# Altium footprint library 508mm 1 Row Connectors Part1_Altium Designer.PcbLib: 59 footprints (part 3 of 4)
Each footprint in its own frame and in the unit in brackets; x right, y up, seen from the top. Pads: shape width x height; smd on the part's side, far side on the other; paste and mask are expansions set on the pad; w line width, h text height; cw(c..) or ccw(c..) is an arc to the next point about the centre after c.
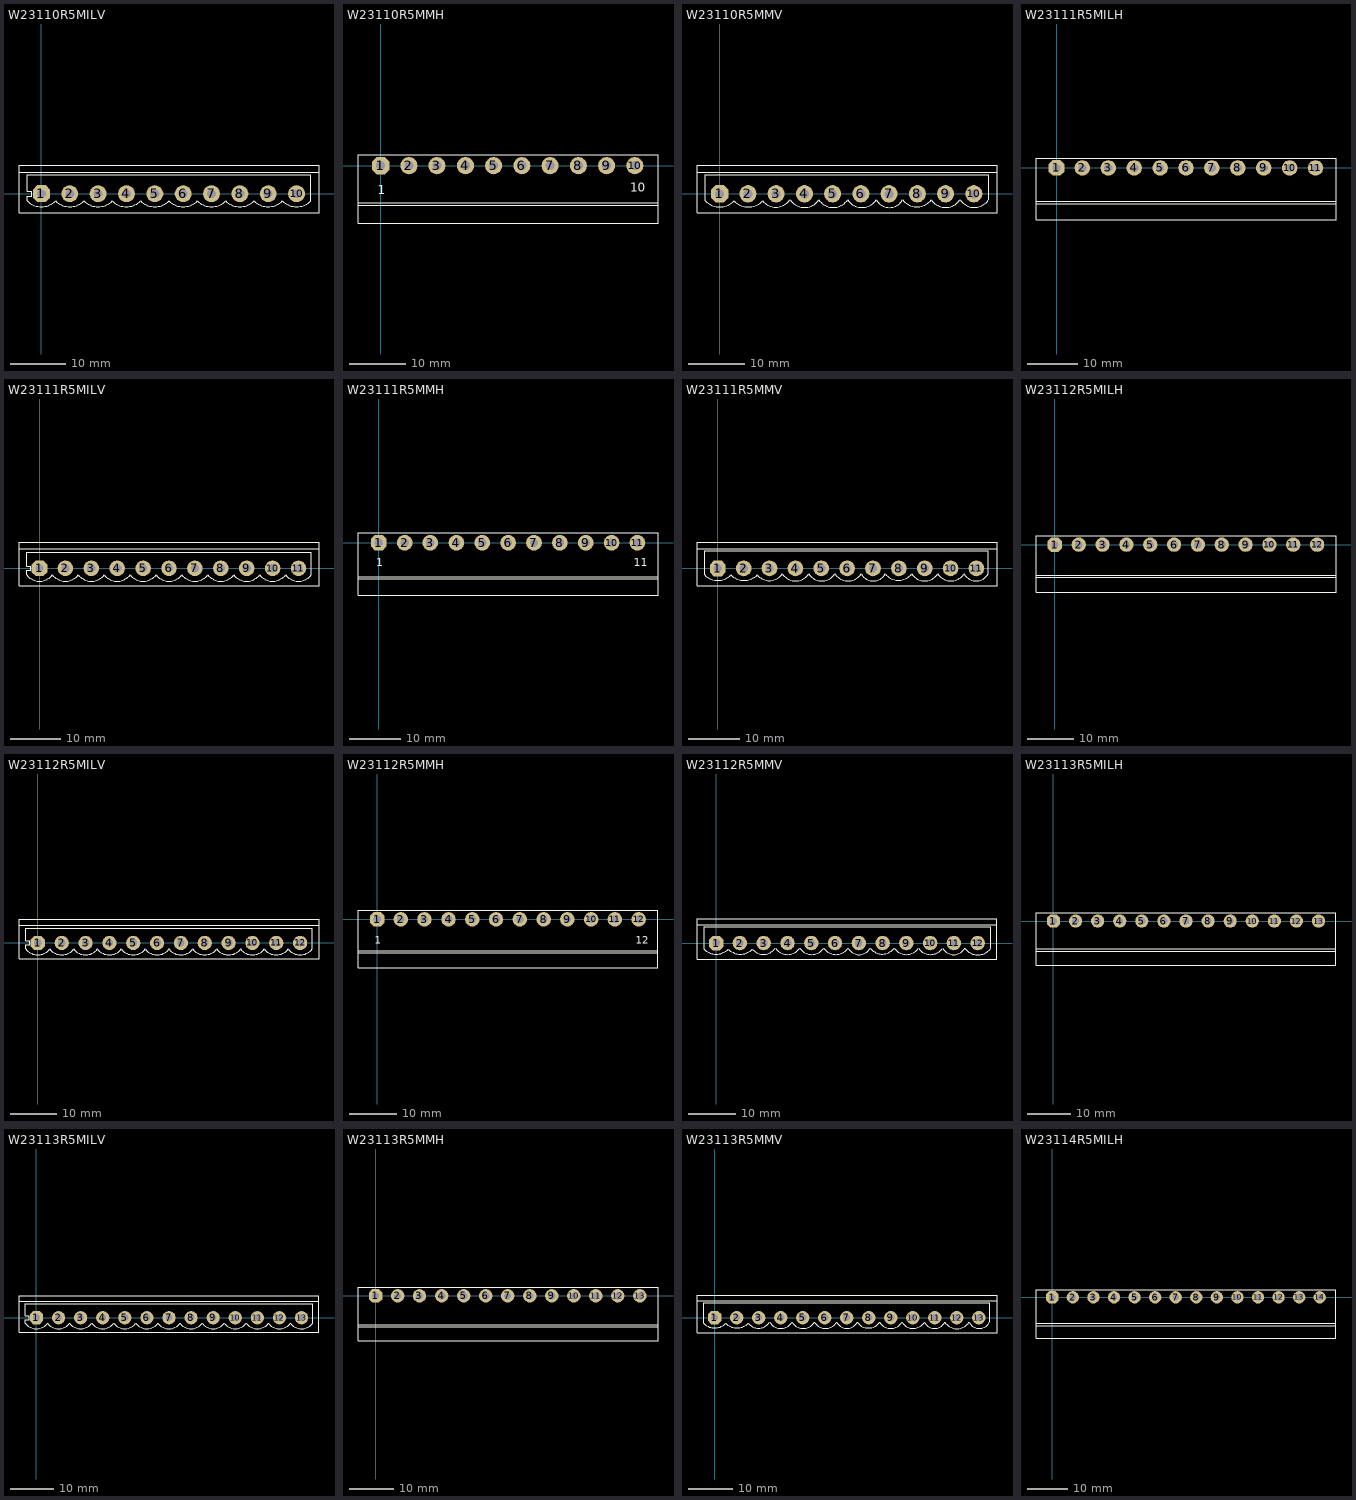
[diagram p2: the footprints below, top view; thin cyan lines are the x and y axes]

## W23110R5MILV [mil] "M.Hariri (Altium Designer)"
pads (10):
  oct 120x120 hole 62.99: 1(0,0)
  round 120 hole 62.99: 2(200,0) 3(400,0) 4(600,0) 5(800,0) 6(1000,0) 7(1200,0) 8(1400,0) 9(1600,0) 10(1800,0)
Top Overlay:
  lines w8: -158.33,150 1958.33,150 ; -100.17,-50.17 ccw(c0,50) 100.17,-50.17 ; -100,-50 -100,-16.67 -66.67,-16.67 -66.67,16.67 -100,16.67 -100,133.33 1900,133.33 1900,-50 ; 99.83,-50.17 ccw(c200,50) 300.17,-50.17 ; 299.83,-50.17 ccw(c400,50) 500.17,-50.17 ; 499.83,-50.17 ccw(c600,50) 700.17,-50.17 ; 699.83,-50.17 ccw(c800,50) 900.17,-50.17 ; 899.83,-50.17 ccw(c1000,50) 1100.17,-50.17 ; 1099.83,-50.17 ccw(c1200,50) 1300.17,-50.17 ; 1299.83,-50.17 ccw(c1400,50) 1500.17,-50.17 ; 1499.83,-50.17 ccw(c1600,50) 1700.17,-50.17 ; 1699.83,-50.17 ccw(c1800,50) 1900.17,-50.17 ; -158.33,-133.33 -158.33,200 1958.33,200 1958.33,-133.33 -158.33,-133.33

## W23110R5MMH [mil] "M.Hariri (Altium Designer)"
pads (10):
  oct 120x120 hole 62.99: 1(0,0)
  round 120 hole 62.99: 2(196.67,0) 3(391.67,0) 4(590.83,0) 5(787.5,0) 6(984.17,0) 7(1180.83,0) 8(1378.33,0) 9(1575,0) 10(1771.67,0)
Top Overlay:
  lines w8: -158.33,-275 1933.33,-275 ; -158.33,-258.33 1933.33,-258.33 ; -158.33,-400 -158.33,75 1933.33,75 1933.33,-400 -158.33,-400
  text "10" at 1740,-180 h60
  text "1" at -20,-200 h60

## W23110R5MMV [mil] "M.Hariri (Altium Designer)"
pads (10):
  oct 120x120 hole 62.99: 1(0,0)
  round 120 hole 62.99: 2(196.67,0) 3(393.33,0) 4(590.83,0) 5(787.5,0) 6(984.17,0) 7(1180.83,0) 8(1378.33,0) 9(1575,0) 10(1771.67,0)
Top Overlay:
  lines w8: -158.33,150 1933.33,150 ; -100.17,-50.17 ccw(c0,50) 100.17,-50.17 ; -100,-50 -100,133.33 1875,133.33 1875,-41.67 ; 99.83,-50.17 ccw(c200,50) 300.17,-50.17 ; 299.7,-49.47 ccw(c391.67,25) 489.77,-41.17 ; 492.18,-42.1 ccw(c591.67,25) 691.15,-42.1 ; 692.18,-42.1 ccw(c791.67,25) 891.15,-42.1 ; 892.18,-42.1 ccw(c991.67,25) 1091.15,-42.1 ; 1092.23,-42.17 ccw(c1183.33,8.33) 1274.44,-42.17 ; 1275.17,-41.89 ccw(c1375,33.33) 1474.83,-41.89 ; 1475.52,-42.1 ccw(c1575,25) 1674.48,-42.1 ; 1675.52,-42.1 ccw(c1775,25) 1872.08,-45.53 ; -158.33,-133.33 1933.33,-133.33 1933.33,200 -158.33,200 -158.33,-133.33

## W23111R5MILH [mil] "M.Hariri (Altium Designer)"
pads (11):
  oct 120x120 hole 62.99: 1(0,0)
  round 120 hole 62.99: 2(200,0) 3(400,0) 4(600,0) 5(800,0) 6(1000,0) 7(1200,0) 8(1400,0) 9(1600,0) 10(1800,0) 11(2000,0)
Top Overlay:
  lines w8: -158.33,-275 2158.33,-275 ; -158.33,-258.33 2158.33,-258.33 ; -158.33,-400 -158.33,75 2158.33,75 2158.33,-400 -158.33,-400

## W23111R5MILV [mil] "M.Hariri (Altium Designer)"
pads (11):
  oct 120x120 hole 62.99: 1(0,0)
  round 120 hole 62.99: 2(200,0) 3(400,0) 4(600,0) 5(800,0) 6(1000,0) 7(1200,0) 8(1400,0) 9(1600,0) 10(1800,0) 11(2000,0)
Top Overlay:
  lines w8: -158.33,150 2158.33,150 ; -100,-50 -100,-16.67 -66.67,-16.67 -66.67,16.67 -100,16.67 -100,125 2100,125 2100,-50 ; -99.83,-50.23 ccw(c0,25) 99.83,-50.23 ; 100.17,-50.23 ccw(c200,25) 299.83,-50.23 ; 300.17,-50.23 ccw(c400,25) 499.83,-50.23 ; 500.17,-50.23 ccw(c600,25) 699.83,-50.23 ; 700.17,-50.23 ccw(c800,25) 899.83,-50.23 ; 900.17,-50.23 ccw(c1000,25) 1099.83,-50.23 ; 1100.17,-50.23 ccw(c1200,25) 1299.83,-50.23 ; 1300.17,-50.23 ccw(c1400,25) 1499.83,-50.23 ; 1500.17,-50.23 ccw(c1600,25) 1699.83,-50.23 ; 1700.17,-50.23 ccw(c1800,25) 1899.83,-50.23 ; 1900.17,-50.23 ccw(c2000,25) 2099.83,-50.23 ; -158.33,-133.33 2158.33,-133.33 2158.33,200 -158.33,200 -158.33,-133.33

## W23111R5MMH [mil] "M.Hariri (Altium Designer)"
pads (11):
  oct 120x120 hole 62.99: 1(0,0)
  round 120 hole 62.99: 2(196.67,0) 3(391.67,0) 4(590.83,0) 5(787.5,0) 6(984.17,0) 7(1180.83,0) 8(1378.33,0) 9(1575,0) 10(1771.67,0) 11(1968.33,0)
Top Overlay:
  lines w8: -158.33,-275 2125,-275 ; -158.33,-258.33 2125,-258.33 ; -158.33,-400 -158.33,75 2125,75 2125,-400 -158.33,-400
  text "1" at -20,-180 h60
  text "11" at 1940,-180 h60

## W23111R5MMV [mil] "M.Hariri (Altium Designer)"
pads (11):
  oct 120x120 hole 62.99: 1(0,0)
  round 120 hole 62.99: 2(196.67,0) 3(393.33,0) 4(590.83,0) 5(787.5,0) 6(984.17,0) 7(1180.83,0) 8(1378.33,0) 9(1575,0) 10(1771.67,0) 11(1968.33,0)
Top Overlay:
  lines w8: -158.33,150 2125,150 ; -100.17,-50.17 ccw(c0,50) 100.17,-50.17 ; -100,-50 -100,133.33 2058.33,133.33 2058.33,-41.67 ; 99.83,-50.17 ccw(c200,50) 300.17,-50.17 ; 299.7,-49.47 ccw(c391.67,25) 489.77,-41.17 ; 492.18,-42.1 ccw(c591.67,25) 691.15,-42.1 ; 692.18,-42.1 ccw(c791.67,25) 891.15,-42.1 ; 892.18,-42.1 ccw(c991.67,25) 1091.15,-42.1 ; 1092.23,-42.17 ccw(c1183.33,8.33) 1274.44,-42.17 ; 1275.17,-41.89 ccw(c1375,33.33) 1474.83,-41.89 ; 1475.52,-42.1 ccw(c1575,25) 1674.48,-42.1 ; 1675.52,-42.1 ccw(c1775,25) 1872.08,-45.53 ; 1875.56,-42.17 ccw(c1966.67,8.33) 2057.77,-42.17 ; -158.33,-133.33 -158.33,200 2125,200 2125,-133.33 -158.33,-133.33

## W23112R5MILH [mil] "M.Hariri (Altium Designer)"
pads (12):
  oct 120x120 hole 62.99: 1(0,0)
  round 120 hole 62.99: 2(200,0) 3(400,0) 4(600,0) 5(800,0) 6(1000,0) 7(1200,0) 8(1400,0) 9(1600,0) 10(1800,0) 11(2000,0) 12(2200,0)
Top Overlay:
  lines w8: -158.33,-275 2358.33,-275 ; -158.33,-258.33 2358.33,-258.33 ; -158.33,-400 2358.33,-400 2358.33,75 -158.33,75 -158.33,-400

## W23112R5MILV [mil] "M.Hariri (Altium Designer)"
pads (12):
  oct 120x120 hole 62.99: 1(0,0)
  round 120 hole 62.99: 2(200,0) 3(400,0) 4(600,0) 5(800,0) 6(1000,0) 7(1200,0) 8(1400,0) 9(1600,0) 10(1800,0) 11(2000,0) 12(2200,0)
Top Overlay:
  lines w8: -158.33,150 2358.33,150 ; -100,-50 -100,-16.67 -66.67,-16.67 -66.67,16.67 -100,16.67 -100,125 2300,125 2300,-50 ; -99.83,-50.23 ccw(c0,25) 99.83,-50.23 ; 100.17,-50.23 ccw(c200,25) 299.83,-50.23 ; 300.17,-50.23 ccw(c400,25) 499.83,-50.23 ; 500.17,-50.23 ccw(c600,25) 699.83,-50.23 ; 700.17,-50.23 ccw(c800,25) 899.83,-50.23 ; 900.17,-50.23 ccw(c1000,25) 1099.83,-50.23 ; 1100.17,-50.23 ccw(c1200,25) 1299.83,-50.23 ; 1300.17,-50.23 ccw(c1400,25) 1499.83,-50.23 ; 1500.17,-50.23 ccw(c1600,25) 1699.83,-50.23 ; 1700.17,-50.23 ccw(c1800,25) 1899.83,-50.23 ; 1900.17,-50.23 ccw(c2000,25) 2099.83,-50.23 ; 2100.17,-50.23 ccw(c2200,25) 2299.83,-50.23 ; -158.33,-133.33 2358.33,-133.33 2358.33,200 -158.33,200 -158.33,-133.33

## W23112R5MMH [mil] "M.Hariri (Altium Designer)"
pads (12):
  oct 120x120 hole 62.99: 1(0,0)
  round 120 hole 62.99: 2(196.67,0) 3(391.67,0) 4(590.83,0) 5(787.5,0) 6(984.17,0) 7(1180.83,0) 8(1378.33,0) 9(1575,0) 10(1771.67,0) 11(1968.33,0) 12(2165,0)
Top Overlay:
  lines w8: -158.33,-275 2325,-275 ; -158.33,-258.33 2325,-258.33 ; -158.33,-400 2325,-400 2325,75 -158.33,75 -158.33,-400
  text "1" at -20,-200 h60
  text "12" at 2140,-200 h60

## W23112R5MMV [mil] "M.Hariri (Altium Designer)"
pads (12):
  oct 120x120 hole 62.99: 1(0,0)
  round 120 hole 62.99: 2(196.67,0) 3(393.33,0) 4(590.83,0) 5(787.5,0) 6(984.17,0) 7(1180.83,0) 8(1378.33,0) 9(1575,0) 10(1771.67,0) 11(1968.33,0) 12(2165,0)
Top Overlay:
  lines w8: -158.33,150 2325,150 ; -100.17,-50.17 ccw(c0,50) 100.17,-50.17 ; -100,-50 -100,133.33 2275,133.33 2275,-41.67 ; 99.83,-50.17 ccw(c200,50) 300.17,-50.17 ; 299.7,-49.47 ccw(c391.67,25) 489.77,-41.17 ; 492.18,-42.1 ccw(c591.67,25) 691.15,-42.1 ; 692.18,-42.1 ccw(c791.67,25) 891.15,-42.1 ; 892.18,-42.1 ccw(c991.67,25) 1091.15,-42.1 ; 1092.23,-42.17 ccw(c1183.33,8.33) 1274.44,-42.17 ; 1275.17,-41.89 ccw(c1375,33.33) 1474.83,-41.89 ; 1475.52,-42.1 ccw(c1575,25) 1674.48,-42.1 ; 1675.52,-42.1 ccw(c1775,25) 1872.08,-45.53 ; 1875.56,-42.17 ccw(c1966.67,8.33) 2057.77,-42.17 ; 2058.81,-42.19 ccw(c2166.67,33.33) 2274.52,-42.19 ; -158.33,-133.33 2325,-133.33 2325,200 -158.33,200 -158.33,-133.33

## W23113R5MILH [mil] "M.Hariri (Altium Designer)"
pads (13):
  oct 120x120 hole 62.99: 1(0,0)
  round 120 hole 62.99: 2(200,0) 3(400,0) 4(600,0) 5(800,0) 6(1000,0) 7(1200,0) 8(1400,0) 9(1600,0) 10(1800,0) 11(2000,0) 12(2200,0) 13(2400,0)
Top Overlay:
  lines w8: -158.33,-275 2558.33,-275 ; -158.33,-250 2558.33,-250 ; -158.33,-400 2558.33,-400 2558.33,75 -158.33,75 -158.33,-400

## W23113R5MILV [mil] "M.Hariri (Altium Designer)"
pads (13):
  oct 120x120 hole 62.99: 1(0,0)
  round 120 hole 62.99: 2(200,0) 3(400,0) 4(600,0) 5(800,0) 6(1000,0) 7(1200,0) 8(1400,0) 9(1600,0) 10(1800,0) 11(2000,0) 12(2200,0) 13(2400,0)
Top Overlay:
  lines w8: -158.33,150 2558.33,150 ; -100,-50 -100,-16.67 -66.67,-16.67 -66.67,16.67 -100,16.67 -100,125 2500,125 2500,-50 ; -99.83,-50.23 ccw(c0,25) 99.83,-50.23 ; 100.17,-50.23 ccw(c200,25) 299.83,-50.23 ; 300.17,-50.23 ccw(c400,25) 499.83,-50.23 ; 500.17,-50.23 ccw(c600,25) 699.83,-50.23 ; 700.17,-50.23 ccw(c800,25) 899.83,-50.23 ; 900.17,-50.23 ccw(c1000,25) 1099.83,-50.23 ; 1100.17,-50.23 ccw(c1200,25) 1299.83,-50.23 ; 1300.17,-50.23 ccw(c1400,25) 1499.83,-50.23 ; 1500.17,-50.23 ccw(c1600,25) 1699.83,-50.23 ; 1700.17,-50.23 ccw(c1800,25) 1899.83,-50.23 ; 1900.17,-50.23 ccw(c2000,25) 2099.83,-50.23 ; 2100.17,-50.23 ccw(c2200,25) 2299.83,-50.23 ; 2300.17,-50.23 ccw(c2400,25) 2499.83,-50.23 ; -158.33,-133.33 -158.33,200 2558.33,200 2558.33,-133.33 -158.33,-133.33

## W23113R5MMH [mil] "M.Hariri (Altium Designer)"
pads (13):
  oct 120x120 hole 62.99: 1(0,0)
  round 120 hole 62.99: 2(196.67,0) 3(391.67,0) 4(590.83,0) 5(787.5,0) 6(984.17,0) 7(1180.83,0) 8(1378.33,0) 9(1575,0) 10(1771.67,0) 11(1968.33,0) 12(2165,0) 13(2362.5,0)
Top Overlay:
  lines w8: -158.33,-275 2525,-275 ; -158.33,-258.33 2525,-258.33 ; -158.33,-400 2525,-400 2525,75 -158.33,75 -158.33,-400

## W23113R5MMV [mil] "M.Hariri (Altium Designer)"
pads (13):
  oct 120x120 hole 62.99: 1(0,0)
  round 120 hole 62.99: 2(196.67,0) 3(393.33,0) 4(590.83,0) 5(787.5,0) 6(984.17,0) 7(1180.83,0) 8(1378.33,0) 9(1575,0) 10(1771.67,0) 11(1968.33,0) 12(2165,0) 13(2362.5,0)
Top Overlay:
  lines w8: -158.33,150 2525,150 ; -100.17,-50.17 ccw(c0,50) 100.17,-50.17 ; -100,-50 -100,133.33 2458.33,133.33 2458.33,-41.67 ; 99.83,-50.17 ccw(c200,50) 300.17,-50.17 ; 299.7,-49.47 ccw(c391.67,25) 489.77,-41.17 ; 492.18,-42.1 ccw(c591.67,25) 691.15,-42.1 ; 692.18,-42.1 ccw(c791.67,25) 891.15,-42.1 ; 892.18,-42.1 ccw(c991.67,25) 1091.15,-42.1 ; 1092.23,-42.17 ccw(c1183.33,8.33) 1274.44,-42.17 ; 1275.17,-41.89 ccw(c1375,33.33) 1474.83,-41.89 ; 1475.52,-42.1 ccw(c1575,25) 1674.48,-42.1 ; 1675.52,-42.1 ccw(c1775,25) 1872.08,-45.53 ; 1875.56,-42.17 ccw(c1966.67,8.33) 2057.77,-42.17 ; 2058.81,-42.19 ccw(c2166.67,33.33) 2274.52,-42.19 ; 2275.56,-42.17 ccw(c2366.67,8.33) 2457.77,-42.17 ; -158.33,-133.33 2525,-133.33 2525,200 -158.33,200 -158.33,-133.33

## W23114R5MILH [mil] "M.Hariri (Altium Designer)"
pads (14):
  oct 120x120 hole 62.99: 1(0,0)
  round 120 hole 62.99: 2(200,0) 3(400,0) 4(600,0) 5(800,0) 6(1000,0) 7(1200,0) 8(1400,0) 9(1600,0) 10(1800,0) 11(2000,0) 12(2200,0) 13(2400,0) 14(2600,0)
Top Overlay:
  lines w8: -158.33,-275 2758.33,-275 ; -158.33,-250 2758.33,-250 ; -158.33,-400 2758.33,-400 2758.33,75 -158.33,75 -158.33,-400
